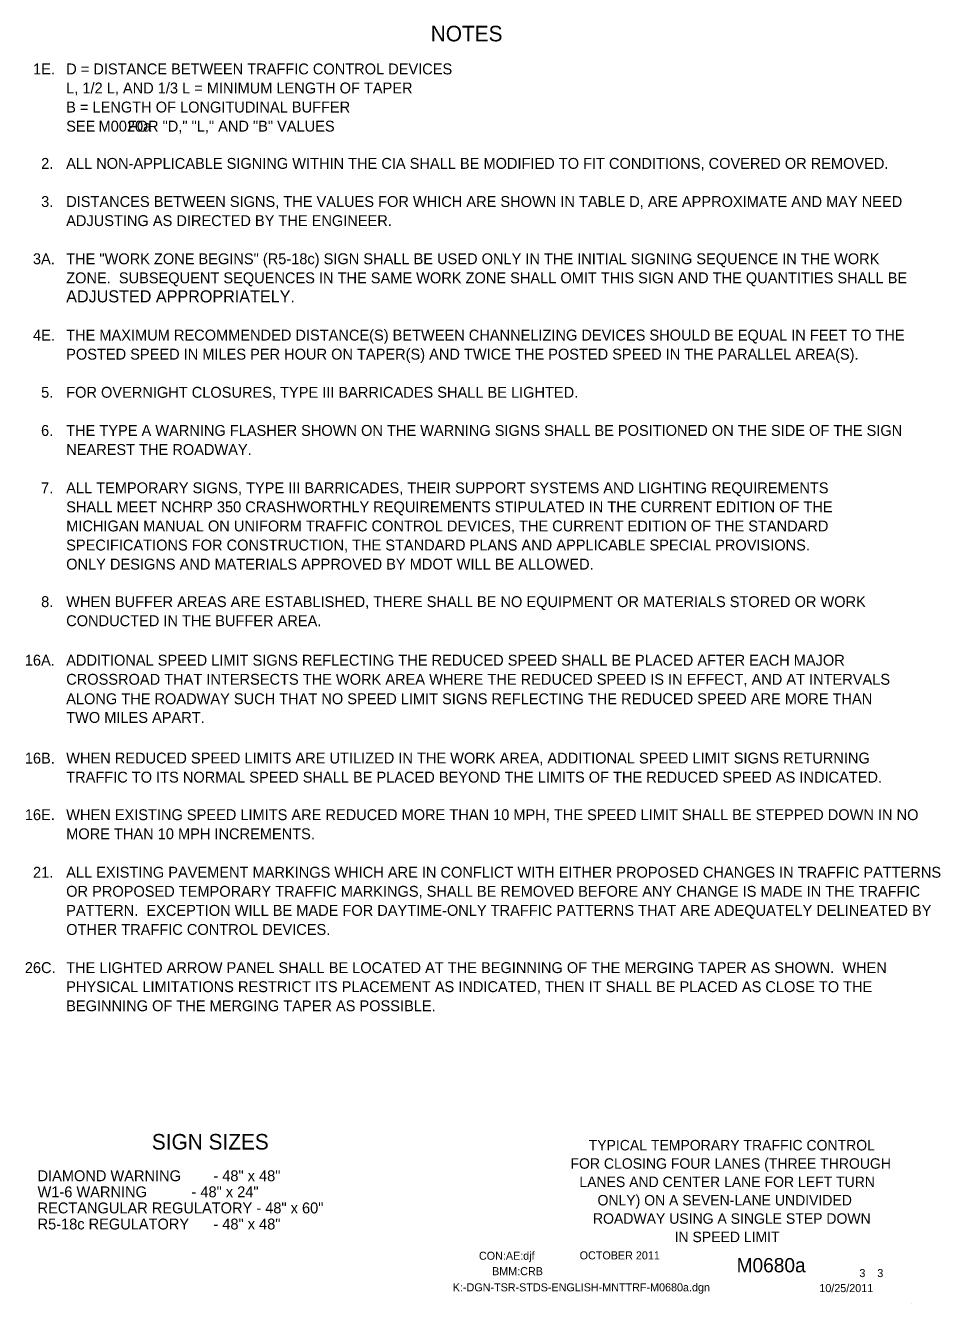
# Model space of a CAD drawing. Extents: x 16038 to 19504, y 5710 to 8321.
# Drawn here: x 18799 to 19504, y 5924 to 6909 of the extents above; entities that cross this region are included whole.
import ezdxf

# ---------------------------------------------------------------- set-up
doc = ezdxf.new("R2010")
doc.units = 0
for name, color, linetype in [('BORDER', 7, 'Continuous'), ('BORDER_SIGNAL_WO', 7, 'Continuous'), ('TYPICAL_TEXT_DIMEN_PR', 7, 'Continuous')]:
    doc.layers.add(name, color=color, linetype=linetype)

msp = doc.modelspace()

# ---------------------------------------------------------------- linework, layer by layer
at = {"layer": 'BORDER'}
for p, q in [((19347.25, 6011.25), (19347.25, 6011.25)), ((19347.25, 6011.25), (19347.25, 6011.25)), ((19481.55, 5924.4), (19481.55, 5924.4))]:
    msp.add_line(p, q, dxfattribs=at)

# ---------------------------------------------------------------- texts
for s, p in [('TYPICAL TEMPORARY TRAFFIC CONTROL', (19233.21, 6042.33)), ('FOR CLOSING FOUR LANES (THREE THROUGH', (19219.21, 6028.2)), ('LANES AND CENTER LANE FOR LEFT TURN', (19226.04, 6014.06)), ('ONLY) ON A SEVEN-LANE UNDIVIDED', (19240.02, 5999.92)), ('ROADWAY USING A SINGLE STEP DOWN', (19236.54, 5985.79)), ('IN SPEED LIMIT', (19299.42, 5971.65))]:
    msp.add_text(s, height=8.066, dxfattribs=at).set_placement(p)
at = {"layer": 'BORDER_SIGNAL_WO'}
for s, height, p in [('CON:AE:djf', 6.2, (19148.69, 5958.06)), ('    OCTOBER 2011    ', 6.2, (19217.08, 5958.34)), ('    M0680a   ', 11, (19330.86, 5948.38)), ('BMM:CRB   ', 6.2, (19158.81, 5946.17)), (' 3    3 ', 6.2, (19439.45, 5944.7)), ('K:-DGN-TSR-STDS-ENGLISH-MNTTRF-M0680a.dgn        ', 6.2, (19128.55, 5933.71)), ('10/25/2011    ', 6.2, (19410.93, 5933.13))]:
    msp.add_text(s, height=height, dxfattribs=at).set_placement(p)
at = {"layer": 'TYPICAL_TEXT_DIMEN_PR'}
for s, height, p in [('NOTES', 12, (19111.55, 6897)), ('1E.', 8.4, (18805.19, 6871.56)), ('D = DISTANCE BETWEEN TRAFFIC CONTROL DEVICES', 8.4, (18830.7, 6871.56)), ('L, 1/2 L, AND 1/3 L = MINIMUM LENGTH OF TAPER', 8.4, (18830.7, 6856.86)), ('B = LENGTH OF LONGITUDINAL BUFFER', 8.4, (18830.7, 6842.16)), ('SEE        FOR "D," "L," AND "B" VALUES', 8.4, (18830.7, 6827.46)), ('M0020a', 8.4, (18855.62, 6827.46)), ('2.', 8.4, (18811.39, 6798.75)), ('ALL NON-APPLICABLE SIGNING WITHIN THE CIA SHALL BE MODIFIED TO FIT CONDITIONS, COVERED OR REMOVED.', 8.4, (18830.7, 6798.75)), ('3.', 8.4, (18811.39, 6769.35)), ('DISTANCES BETWEEN SIGNS, THE VALUES FOR WHICH ARE SHOWN IN TABLE D, ARE APPROXIMATE AND MAY NEED', 8.4, (18830.7, 6769.35)), ('ADJUSTING AS DIRECTED BY THE ENGINEER.', 8.4, (18830.7, 6754.65)), ('3A.', 8.4, (18805.09, 6725.25)), ('THE "WORK ZONE BEGINS" (R5-18c) SIGN SHALL BE USED ONLY IN THE INITIAL SIGNING SEQUENCE IN THE WORK', 8.4, (18830.7, 6725.25)), ('ZONE.  SUBSEQUENT SEQUENCES IN THE SAME WORK ZONE SHALL OMIT THIS SIGN AND THE QUANTITIES SHALL BE', 8.4, (18830.7, 6710.55)), ('ADJUSTED APPROPRIATELY.', 9.3, (18830.7, 6695.85)), ('4E.', 8.4, (18805.13, 6666.45)), ('THE MAXIMUM RECOMMENDED DISTANCE(S) BETWEEN CHANNELIZING DEVICES SHOULD BE EQUAL IN FEET TO THE', 8.4, (18830.7, 6666.45)), ('POSTED SPEED IN MILES PER HOUR ON TAPER(S) AND TWICE THE POSTED SPEED IN THE PARALLEL AREA(S).', 8.4, (18830.7, 6651.75)), ('5.', 8.4, (18811.39, 6622.35)), ('FOR OVERNIGHT CLOSURES, TYPE III BARRICADES SHALL BE LIGHTED.', 8.4, (18830.7, 6622.35)), ('6.', 8.4, (18811.34, 6592.95)), ('THE TYPE A WARNING FLASHER SHOWN ON THE WARNING SIGNS SHALL BE POSITIONED ON THE SIDE OF THE SIGN', 8.4, (18830.7, 6592.95)), ('NEAREST THE ROADWAY.', 8.4, (18830.7, 6578.25)), ('7.', 8.4, (18811.34, 6548.73)), ('ALL TEMPORARY SIGNS, TYPE III BARRICADES, THEIR SUPPORT SYSTEMS AND LIGHTING REQUIREMENTS', 8.4, (18830.7, 6548.75)), ('SHALL MEET NCHRP 350 CRASHWORTHLY REQUIREMENTS STIPULATED IN THE CURRENT EDITION OF THE', 8.4, (18830.7, 6534.05)), ('MICHIGAN MANUAL ON UNIFORM TRAFFIC CONTROL DEVICES, THE CURRENT EDITION OF THE STANDARD', 8.4, (18830.7, 6519.35)), ('SPECIFICATIONS FOR CONSTRUCTION, THE STANDARD PLANS AND APPLICABLE SPECIAL PROVISIONS.', 8.4, (18830.7, 6504.65)), ('ONLY DESIGNS AND MATERIALS APPROVED BY MDOT WILL BE ALLOWED.', 8.4, (18830.7, 6489.95)), ('8.', 8.4, (18811.39, 6461.01)), ('WHEN BUFFER AREAS ARE ESTABLISHED, THERE SHALL BE NO EQUIPMENT OR MATERIALS STORED OR WORK     ', 8.4, (18830.7, 6461.01)), ('CONDUCTED IN THE BUFFER AREA.', 8.4, (18830.7, 6446.31)), ('16A.', 8.4, (18798.83, 6415.89)), ('ADDITIONAL SPEED LIMIT SIGNS REFLECTING THE REDUCED SPEED SHALL BE PLACED AFTER EACH MAJOR', 8.4, (18830.7, 6415.89)), ('CROSSROAD THAT INTERSECTS THE WORK AREA WHERE THE REDUCED SPEED IS IN EFFECT, AND AT INTERVALS', 8.4, (18830.7, 6401.19)), ('ALONG THE ROADWAY SUCH THAT NO SPEED LIMIT SIGNS REFLECTING THE REDUCED SPEED ARE MORE THAN', 8.4, (18830.7, 6386.19)), ('TWO MILES APART.', 8.4, (18830.7, 6371.79)), ('16B.', 8.4, (18798.84, 6340.45)), ('WHEN REDUCED SPEED LIMITS ARE UTILIZED IN THE WORK AREA, ADDITIONAL SPEED LIMIT SIGNS RETURNING', 8.4, (18830.7, 6340.5)), ('TRAFFIC TO ITS NORMAL SPEED SHALL BE PLACED BEYOND THE LIMITS OF THE REDUCED SPEED AS INDICATED.', 8.4, (18830.7, 6325.8)), ('16E.', 8.4, (18798.84, 6296.83)), ('WHEN EXISTING SPEED LIMITS ARE REDUCED MORE THAN 10 MPH, THE SPEED LIMIT SHALL BE STEPPED DOWN IN NO', 8.4, (18830.7, 6296.83)), ('MORE THAN 10 MPH INCREMENTS.', 8.4, (18830.7, 6282.13)), ('21.', 8.4, (18805.14, 6252.49)), ('ALL EXISTING PAVEMENT MARKINGS WHICH ARE IN CONFLICT WITH EITHER PROPOSED CHANGES IN TRAFFIC PATTERNS', 8.4, (18830.7, 6252.49)), ('OR PROPOSED TEMPORARY TRAFFIC MARKINGS, SHALL BE REMOVED BEFORE ANY CHANGE IS MADE IN THE TRAFFIC', 8.4, (18830.7, 6237.79)), ('PATTERN.  EXCEPTION WILL BE MADE FOR DAYTIME-ONLY TRAFFIC PATTERNS THAT ARE ADEQUATELY DELINEATED BY', 8.4, (18830.7, 6223.09)), ('OTHER TRAFFIC CONTROL DEVICES.', 8.4, (18830.7, 6208.39)), ('26C.', 8.4, (18798.83, 6178.99)), ('THE LIGHTED ARROW PANEL SHALL BE LOCATED AT THE BEGINNING OF THE MERGING TAPER AS SHOWN.  WHEN', 8.4, (18830.7, 6178.99)), ('PHYSICAL LIMITATIONS RESTRICT ITS PLACEMENT AS INDICATED, THEN IT SHALL BE PLACED AS CLOSE TO THE', 8.4, (18830.7, 6164.29)), ('BEGINNING OF THE MERGING TAPER AS POSSIBLE.', 8.4, (18830.7, 6149.59)), ('SIGN SIZES', 12, (18896.69, 6043)), ('DIAMOND WARNING        - 48" x 48"', 8.4, (18808.65, 6018.6)), ('W1-6 WARNING           - 48" x 24"', 8.4, (18808.65, 6006.2)), ('RECTANGULAR REGULATORY - 48" x 60"', 8.4, (18808.65, 5993.8)), ('R5-18c REGULATORY      - 48" x 48"', 8.4, (18808.65, 5981.4))]:
    msp.add_text(s, height=height, dxfattribs=at).set_placement(p)

doc.saveas('drawing.dxf')
